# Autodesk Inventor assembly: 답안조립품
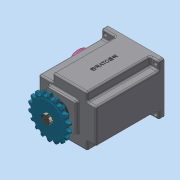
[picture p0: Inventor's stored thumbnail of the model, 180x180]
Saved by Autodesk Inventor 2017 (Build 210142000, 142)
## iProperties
Part Number: 답안조립품
Material: 일반
Document SubType Name: Assembly
Designer: MRC
Author: MRC
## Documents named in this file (16)
- C:\Users\MRC\Desktop\720212V1006\답안조립품.iam
- C:\Users\MRC\Desktop\720212V1006\본체.ipt
- C:\Users\MRC\Desktop\720212V1006\멈춤나사 M3.ipt
- C:\Users\MRC\Desktop\720212V1006\메인 축.ipt
- C:\Users\MRC\Desktop\720212V1006\베어링 608.ipt
- C:\Users\MRC\Desktop\720212V1006\베어링 6003.ipt
- C:\Users\MRC\Desktop\720212V1006\볼트 M4 x 10.ipt
- C:\Users\MRC\Desktop\720212V1006\부시.ipt
- C:\Users\MRC\Desktop\720212V1006\상부 캡.ipt
- C:\Users\MRC\Desktop\720212V1006\서브 축.ipt
- C:\Users\MRC\Desktop\720212V1006\스프로킷.ipt
- C:\Users\MRC\Desktop\720212V1006\슬라이더.ipt
- C:\Users\MRC\Desktop\720212V1006\오일 실 8 x 22 x 7.ipt
- C:\Users\MRC\Desktop\720212V1006\오일 실 17 x 32 x 8.ipt
- C:\Users\MRC\Desktop\720212V1006\커버.ipt
- C:\Users\MRC\Desktop\720212V1006\키 5 x 5.ipt
